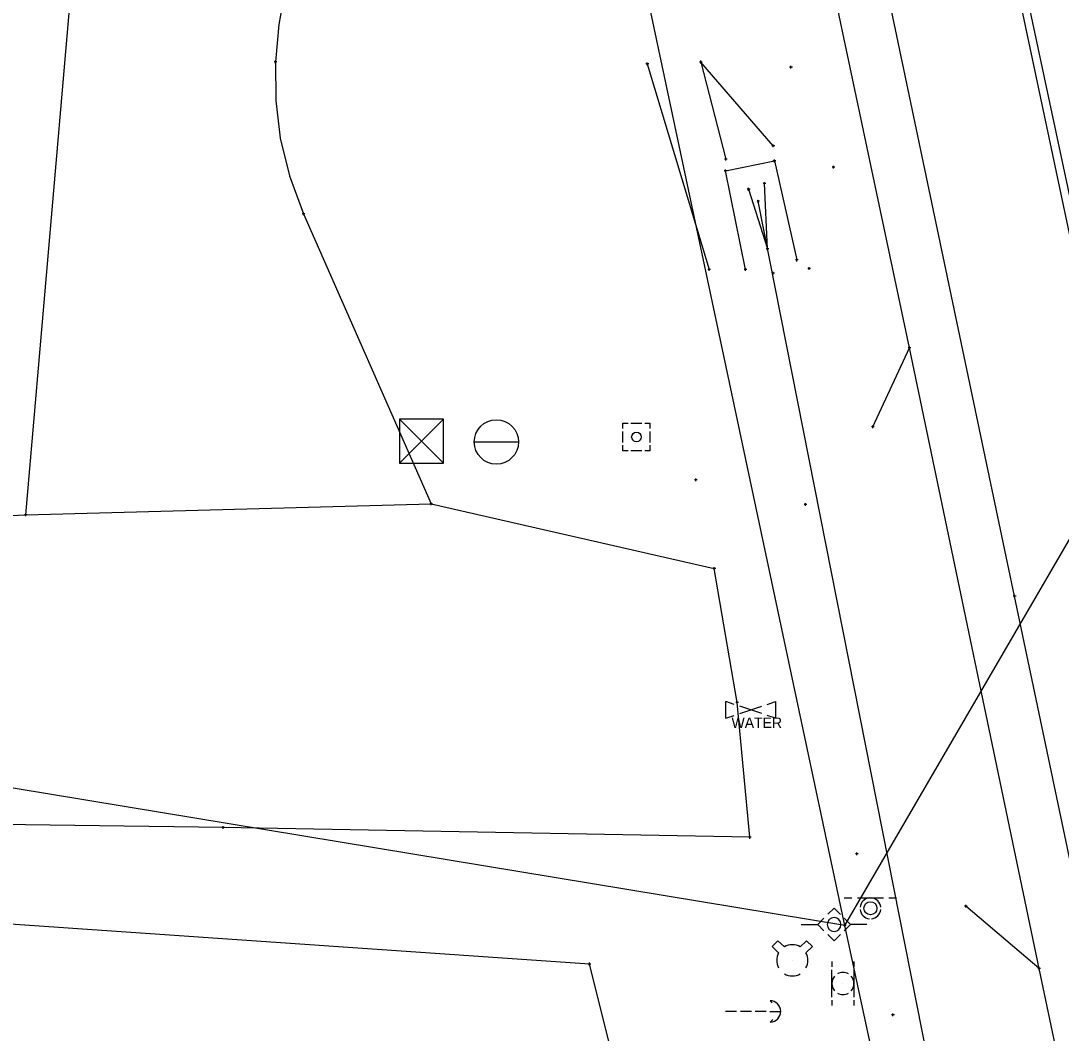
# Model space of a CAD drawing. Extents: x 1954856 to 2011933, y 399149 to 426294.
# Drawn here: x 2005370.7 to 2005465.1, y 405686.9 to 405778.8 of the extents above; entities that cross this region are included whole.
import ezdxf

# ---------------------------------------------------------------- set-up
doc = ezdxf.new("R2010")
doc.units = 0
for name, color, linetype in [('BankMent_ep', 7, 'Continuous'), ('BaselineSurvey', 7, 'Continuous'), ('DelineatorPost_ep', 7, 'Continuous'), ('Driveway_ep', 7, 'Continuous'), ('ElecAer_ep', 7, 'Continuous'), ('EndTreatMES_ep', 7, 'Continuous'), ('FireHydrant_ep', 7, 'Continuous'), ('FlowLineInvert_ep', 7, 'Continuous'), ('GuyWireAnchor_ep', 7, 'Continuous'), ('MonumentOM_ep', 7, 'Continuous'), ('MonumentPST_ep', 7, 'Continuous'), ('PavtAsphalt_ep', 7, 'Continuous'), ('PavtAsphaltCrown_ep', 7, 'Continuous'), ('PipeCulvert_ep', 7, 'Continuous'), ('PointLocator_ep', 7, 'Continuous'), ('PoleShared_ep', 7, 'Continuous'), ('ShldrPaved_ep', 7, 'Continuous'), ('SignSingle_ep', 7, 'Continuous'), ('TelePed_ep', 7, 'Continuous'), ('Trail_ep', 7, 'Continuous'), ('TreeLineScatter_ep', 7, 'Continuous'), ('ValveWater_ep', 7, 'Continuous')]:
    doc.layers.add(name, color=color, linetype=linetype)

msp = doc.modelspace()

# ---------------------------------------------------------------- linework, layer by layer
at = {"layer": 'BankMent_ep'}
msp.add_line((2005427.558, 405774.906), (2005433.178, 405756.239), dxfattribs=at)
msp.add_lwpolyline([(2005438.996, 405767.47), (2005432.422, 405775.077), (2005434.694, 405766.254)], dxfattribs=at)
at = {"layer": 'BaselineSurvey'}
msp.add_line((2006223.925, 402174.382), (2005094.479, 407516.047), dxfattribs=at)
msp.add_line((2006223.925, 402174.382), (2005094.479, 407516.047), dxfattribs=at)
at = {"layer": 'DelineatorPost_ep'}
for p, q in [((2005444.314, 405693.447), (2005444.314, 405692.947)), ((2005446.314, 405693.447), (2005446.314, 405692.947)), ((2005444.314, 405690.197), (2005444.314, 405692.697)), ((2005446.314, 405692.697), (2005446.314, 405690.197)), ((2005445.314, 405691.447), (2005445.314, 405691.447)), ((2005444.314, 405689.947), (2005444.314, 405689.447)), ((2005446.314, 405689.947), (2005446.314, 405689.447))]:
    msp.add_line(p, q, dxfattribs=at)
for start, end in [(138.59038, 221.40962), (60, 120), (318.59038, 41.40962), (240, 300)]:
    msp.add_arc((2005445.314, 405691.447), 1, start, end, dxfattribs=at)
at = {"layer": 'Driveway_ep'}
for p, q in [((2005371.12, 405733.975), (2005375.351, 405782.839)), ((2005396.341, 405761.312), (2005407.925, 405734.989)), ((2005448.023, 405741.963), (2005451.367, 405749.131)), ((2005435.705, 405716.948), (2005433.64, 405729.119)), ((2005436.858, 405704.714), (2005435.705, 405716.948)), ((2005463.131, 405692.797), (2005456.475, 405698.46))]:
    msp.add_line(p, q, dxfattribs=at)
msp.add_lwpolyline([(2005417.945, 405803.487), (2005414.759, 405802.733), (2005411.798, 405801.807), (2005409.062, 405800.694), (2005406.551, 405799.379), (2005404.264, 405797.848), (2005402.2, 405796.084), (2005400.36, 405794.072), (2005398.482, 405791.387), (2005396.914, 405788.413), (2005395.658, 405785.222), (2005394.716, 405781.888), (2005394.092, 405778.485), (2005393.787, 405775.084), (2005393.817, 405771.592), (2005394.232, 405768.153), (2005395.062, 405764.737), (2005396.341, 405761.312)], dxfattribs=at)
at = {"layer": 'ElecAer_ep'}
for points in [[(2005445.498, 405696.718), (2005374.403, 406031.294), (2005427.328, 406130.782), (2005454.704, 406142.236)], [(2005445.498, 405696.718), (2005506.92, 405802.26), (2005520.719, 405804.021)], [(2005486.91, 405504.756), (2005445.498, 405696.718), (2005301.203, 405720.515)]]:
    msp.add_lwpolyline(points, dxfattribs=at)
at = {"layer": 'EndTreatMES_ep'}
for p, q in [((2005434.655, 405765.204), (2005439.091, 405766.098)), ((2005439.091, 405766.098), (2005441.134, 405757.112)), ((2005436.466, 405756.253), (2005434.655, 405765.204))]:
    msp.add_line(p, q, dxfattribs=at)
msp.add_lwpolyline([(2005436.758, 405763.527), (2005438.46, 405758.117), (2005438.204, 405764.048)], dxfattribs=at)
at = {"layer": 'FireHydrant_ep'}
for p, q in [((2005438.893, 405694.794), (2005439.418, 405695.331)), ((2005438.893, 405694.794), (2005439.478, 405694.228)), ((2005439.418, 405695.331), (2005440.001, 405694.768)), ((2005442.021, 405695.328), (2005441.441, 405694.768)), ((2005442.546, 405694.791), (2005441.964, 405694.228)), ((2005442.546, 405694.791), (2005442.021, 405695.328)), ((2005440.721, 405693.547), (2005440.721, 405693.547))]:
    msp.add_line(p, q, dxfattribs=at)
for start, end in [(59.47352, 120.52648), (151.26736, 208.73264), (331.26736, 28.73264), (239.47352, 300.52648)]:
    msp.add_arc((2005440.721, 405693.547), 1.417, start, end, dxfattribs=at)
at = {"layer": 'FlowLineInvert_ep'}
for p, q in [((2005437.713, 405762.355), (2005437.537, 405762.531)), ((2005437.713, 405762.531), (2005437.537, 405762.355)), ((2005437.625, 405762.443), (2005437.625, 405762.443))]:
    msp.add_line(p, q, dxfattribs=at)
at = {"layer": 'GuyWireAnchor_ep'}
for p, q in [((2005438.697, 405689.887), (2005438.89, 405689.694)), ((2005434.67, 405688.924), (2005435.67, 405688.924)), ((2005436.003, 405688.924), (2005437.003, 405688.924)), ((2005437.337, 405688.924), (2005438.337, 405688.924)), ((2005438.67, 405688.914), (2005439.67, 405688.914)), ((2005438.712, 405687.941), (2005438.95, 405688.174)), ((2005439.67, 405688.914), (2005439.67, 405688.914))]:
    msp.add_line(p, q, dxfattribs=at)
msp.add_arc((2005438.697, 405688.914), 0.973, 271.13997, 90.0059, dxfattribs=at)
at = {"layer": 'MonumentOM_ep'}
for p, q in [((2005411.841, 405740.594), (2005415.859, 405740.594)), ((2005413.85, 405740.594), (2005413.85, 405740.594))]:
    msp.add_line(p, q, dxfattribs=at)
msp.add_circle((2005413.85, 405740.594), 2.009, dxfattribs=at)
at = {"layer": 'MonumentPST_ep'}
for p, q in [((2005405.047, 405742.672), (2005409.051, 405738.668)), ((2005405.047, 405738.668), (2005409.051, 405742.672)), ((2005407.049, 405740.67), (2005407.049, 405740.67))]:
    msp.add_line(p, q, dxfattribs=at)
msp.add_lwpolyline([(2005405.047, 405738.668), (2005409.051, 405738.668), (2005409.051, 405742.672), (2005405.047, 405742.672), (2005405.047, 405738.668)], dxfattribs=at)
at = {"layer": 'PavtAsphalt_ep'}
msp.add_lwpolyline([(2005647.527, 404845.36), (2005626.419, 404943.283), (2005605.825, 405041.291), (2005585.161, 405139.301), (2005564.569, 405237.066), (2005543.611, 405334.993), (2005527.25, 405416.168), (2005502.474, 405530.372), (2005481.578, 405628.348), (2005460.909, 405726.598), (2005440.426, 405824.017), (2005419.925, 405921.902), (2005399.287, 406019.762)], dxfattribs=at)
at = {"layer": 'PavtAsphaltCrown_ep'}
msp.add_lwpolyline([(2005659.531, 404847.945), (2005638.673, 404945.697), (2005617.909, 405043.694), (2005597.24, 405141.46), (2005576.514, 405239.298), (2005555.953, 405336.916), (2005535.174, 405434.816), (2005514.411, 405532.803), (2005493.563, 405630.595), (2005473.232, 405728.595), (2005452.357, 405826.425), (2005431.937, 405924.199), (2005411.143, 406022.056)], dxfattribs=at)
at = {"layer": 'PipeCulvert_ep'}
msp.add_lwpolyline([(2005456.117, 405668.938), (2005437.625, 405762.443)], dxfattribs=at)
at = {"layer": 'PointLocator_ep'}
for p, q in [((2005393.912, 405775.084), (2005393.662, 405775.084)), ((2005393.787, 405774.959), (2005393.787, 405775.209)), ((2005393.787, 405775.084), (2005393.787, 405775.084)), ((2005427.683, 405774.906), (2005427.433, 405774.906)), ((2005427.558, 405774.781), (2005427.558, 405775.031)), ((2005427.558, 405774.906), (2005427.558, 405774.906)), ((2005432.547, 405775.077), (2005432.297, 405775.077)), ((2005432.422, 405774.952), (2005432.422, 405775.202)), ((2005432.422, 405775.077), (2005432.422, 405775.077)), ((2005440.726, 405774.618), (2005440.476, 405774.618)), ((2005440.601, 405774.493), (2005440.601, 405774.743)), ((2005440.601, 405774.618), (2005440.601, 405774.618)), ((2005439.121, 405767.47), (2005438.871, 405767.47)), ((2005438.996, 405767.345), (2005438.996, 405767.595)), ((2005438.996, 405767.47), (2005438.996, 405767.47)), ((2005434.819, 405766.254), (2005434.569, 405766.254)), ((2005434.694, 405766.129), (2005434.694, 405766.379)), ((2005434.694, 405766.254), (2005434.694, 405766.254)), ((2005439.216, 405766.098), (2005438.966, 405766.098)), ((2005439.091, 405765.973), (2005439.091, 405766.223)), ((2005439.091, 405766.098), (2005439.091, 405766.098)), ((2005444.585, 405765.545), (2005444.335, 405765.545)), ((2005444.46, 405765.42), (2005444.46, 405765.67)), ((2005444.46, 405765.545), (2005444.46, 405765.545)), ((2005434.78, 405765.204), (2005434.53, 405765.204)), ((2005434.655, 405765.079), (2005434.655, 405765.329)), ((2005434.655, 405765.204), (2005434.655, 405765.204)), ((2005436.758, 405763.402), (2005436.758, 405763.652)), ((2005438.329, 405764.048), (2005438.079, 405764.048)), ((2005438.204, 405763.923), (2005438.204, 405764.173)), ((2005438.204, 405764.048), (2005438.204, 405764.048)), ((2005436.883, 405763.527), (2005436.633, 405763.527)), ((2005436.758, 405763.527), (2005436.758, 405763.527)), ((2005396.466, 405761.312), (2005396.216, 405761.312)), ((2005396.341, 405761.187), (2005396.341, 405761.437)), ((2005396.341, 405761.312), (2005396.341, 405761.312)), ((2005438.585, 405758.117), (2005438.335, 405758.117)), ((2005438.46, 405757.992), (2005438.46, 405758.242)), ((2005438.46, 405758.117), (2005438.46, 405758.117)), ((2005441.259, 405757.112), (2005441.009, 405757.112)), ((2005441.134, 405756.987), (2005441.134, 405757.237)), ((2005441.134, 405757.112), (2005441.134, 405757.112)), ((2005433.303, 405756.239), (2005433.053, 405756.239)), ((2005433.178, 405756.114), (2005433.178, 405756.364)), ((2005433.178, 405756.239), (2005433.178, 405756.239)), ((2005436.591, 405756.253), (2005436.341, 405756.253)), ((2005436.466, 405756.128), (2005436.466, 405756.378)), ((2005436.466, 405756.253), (2005436.466, 405756.253)), ((2005438.974, 405755.799), (2005438.974, 405756.049)), ((2005442.368, 405756.337), (2005442.118, 405756.337)), ((2005442.243, 405756.212), (2005442.243, 405756.462)), ((2005442.243, 405756.337), (2005442.243, 405756.337)), ((2005439.099, 405755.924), (2005438.849, 405755.924)), ((2005438.974, 405755.924), (2005438.974, 405755.924)), ((2005451.492, 405749.131), (2005451.242, 405749.131)), ((2005451.367, 405749.006), (2005451.367, 405749.256)), ((2005451.367, 405749.131), (2005451.367, 405749.131)), ((2005448.148, 405741.963), (2005447.898, 405741.963)), ((2005448.023, 405741.838), (2005448.023, 405742.088)), ((2005448.023, 405741.963), (2005448.023, 405741.963)), ((2005432.089, 405737.167), (2005431.839, 405737.167)), ((2005431.964, 405737.042), (2005431.964, 405737.292)), ((2005431.964, 405737.167), (2005431.964, 405737.167)), ((2005408.05, 405734.989), (2005407.8, 405734.989)), ((2005407.925, 405734.864), (2005407.925, 405735.114)), ((2005407.925, 405734.989), (2005407.925, 405734.989)), ((2005442.038, 405734.931), (2005441.788, 405734.931)), ((2005441.913, 405734.806), (2005441.913, 405735.056)), ((2005441.913, 405734.931), (2005441.913, 405734.931)), ((2005371.245, 405733.975), (2005370.995, 405733.975)), ((2005371.12, 405733.85), (2005371.12, 405734.1)), ((2005371.12, 405733.975), (2005371.12, 405733.975)), ((2005433.765, 405729.119), (2005433.515, 405729.119)), ((2005433.64, 405728.994), (2005433.64, 405729.244)), ((2005433.64, 405729.119), (2005433.64, 405729.119)), ((2005460.909, 405726.473), (2005460.909, 405726.723)), ((2005461.034, 405726.598), (2005460.784, 405726.598)), ((2005460.909, 405726.598), (2005460.909, 405726.598)), ((2005435.83, 405716.948), (2005435.58, 405716.948)), ((2005435.705, 405716.823), (2005435.705, 405717.073)), ((2005435.705, 405716.948), (2005435.705, 405716.948)), ((2005389.167, 405705.615), (2005388.917, 405705.615)), ((2005389.042, 405705.49), (2005389.042, 405705.74)), ((2005389.042, 405705.615), (2005389.042, 405705.615)), ((2005436.983, 405704.714), (2005436.733, 405704.714)), ((2005436.858, 405704.589), (2005436.858, 405704.839)), ((2005436.858, 405704.714), (2005436.858, 405704.714)), ((2005446.711, 405703.21), (2005446.461, 405703.21)), ((2005446.586, 405703.085), (2005446.586, 405703.335)), ((2005446.586, 405703.21), (2005446.586, 405703.21)), ((2005456.6, 405698.46), (2005456.35, 405698.46)), ((2005456.475, 405698.335), (2005456.475, 405698.585)), ((2005456.475, 405698.46), (2005456.475, 405698.46)), ((2005445.623, 405696.718), (2005445.373, 405696.718)), ((2005445.498, 405696.593), (2005445.498, 405696.843)), ((2005445.498, 405696.718), (2005445.498, 405696.718)), ((2005422.43, 405693.214), (2005422.18, 405693.214)), ((2005422.305, 405693.089), (2005422.305, 405693.339)), ((2005422.305, 405693.214), (2005422.305, 405693.214)), ((2005463.256, 405692.797), (2005463.006, 405692.797)), ((2005463.131, 405692.672), (2005463.131, 405692.922)), ((2005463.131, 405692.797), (2005463.131, 405692.797)), ((2005449.986, 405688.614), (2005449.736, 405688.614)), ((2005449.861, 405688.489), (2005449.861, 405688.739)), ((2005449.861, 405688.614), (2005449.861, 405688.614))]:
    msp.add_line(p, q, dxfattribs=at)
at = {"layer": 'PoleShared_ep'}
for p, q in [((2005441.528, 405696.802), (2005443.028, 405696.802)), ((2005443.028, 405696.802), (2005443.595, 405697.369)), ((2005443.59, 405696.241), (2005443.028, 405696.802)), ((2005444.516, 405696.802), (2005444.516, 405696.802)), ((2005447.504, 405696.802), (2005446.004, 405696.802))]:
    msp.add_line(p, q, dxfattribs=at)
for points in [[(2005443.951, 405697.725), (2005444.516, 405698.29), (2005445.083, 405697.723)], [(2005445.438, 405697.368), (2005446.004, 405696.802), (2005445.437, 405696.235)], [(2005445.083, 405695.881), (2005444.516, 405695.314), (2005443.949, 405695.881)]]:
    msp.add_lwpolyline(points, dxfattribs=at)
for start, end in [(90, 270), (270, 90)]:
    msp.add_arc((2005444.516, 405696.802), 0.625, start, end, dxfattribs=at)
at = {"layer": 'ShldrPaved_ep'}
msp.add_lwpolyline([(2005642.79, 404844.426), (2005626.089, 404922.973), (2005619.586, 404953.5), (2005603.976, 405028.203), (2005595.201, 405068.867), (2005580.618, 405138.253), (2005559.729, 405235.858), (2005538.961, 405333.935), (2005522.845, 405410.169), (2005520.122, 405422.327), (2005518.168, 405431.543), (2005497.797, 405529.428), (2005476.915, 405627.442), (2005463.131, 405692.797), (2005451.367, 405749.131), (2005441.124, 405797.497), (2005431.885, 405841.855), (2005414.859, 405921.033), (2005394.473, 406019.032)], dxfattribs=at)
at = {"layer": 'SignSingle_ep'}
for p, q in [((2005445.441, 405699.223), (2005446.141, 405699.223)), ((2005446.641, 405699.223), (2005448.991, 405699.223)), ((2005449.491, 405699.223), (2005450.191, 405699.223)), ((2005447.816, 405698.273), (2005447.816, 405698.273))]:
    msp.add_line(p, q, dxfattribs=at)
msp.add_circle((2005447.816, 405698.273), 0.594, dxfattribs=at)
for start, end in [(96.04233, 173.95767), (6.04233, 83.95767), (186.04233, 263.95767), (276.04233, 353.95767)]:
    msp.add_arc((2005447.816, 405698.273), 0.95, start, end, dxfattribs=at)
at = {"layer": 'TelePed_ep'}
for p, q in [((2005425.324, 405742.304), (2005425.824, 405742.304)), ((2005425.324, 405741.804), (2005425.324, 405742.304)), ((2005426.074, 405742.304), (2005427.074, 405742.304)), ((2005427.324, 405742.304), (2005427.824, 405742.304)), ((2005427.824, 405741.804), (2005427.824, 405742.304)), ((2005425.324, 405740.554), (2005425.324, 405741.554)), ((2005426.574, 405741.054), (2005426.574, 405741.054)), ((2005427.824, 405740.554), (2005427.824, 405741.554)), ((2005425.324, 405739.804), (2005425.324, 405740.304)), ((2005427.824, 405739.804), (2005427.824, 405740.304)), ((2005425.824, 405739.804), (2005425.324, 405739.804)), ((2005427.074, 405739.804), (2005426.074, 405739.804)), ((2005427.824, 405739.804), (2005427.324, 405739.804))]:
    msp.add_line(p, q, dxfattribs=at)
msp.add_circle((2005426.574, 405741.054), 0.438, dxfattribs=at)
at = {"layer": 'Trail_ep'}
for points in [[(2005300.132, 405730.93), (2005371.12, 405733.975), (2005407.925, 405734.989), (2005433.64, 405729.119)], [(2005436.858, 405704.714), (2005389.042, 405705.615), (2005303.684, 405706.751)]]:
    msp.add_lwpolyline(points, dxfattribs=at)
at = {"layer": 'TreeLineScatter_ep'}
msp.add_lwpolyline([(2005459.854, 405543.214), (2005422.305, 405693.214), (2005304.819, 405701.308)], dxfattribs=at)
at = {"layer": 'ValveWater_ep'}
for p, q in [((2005435.443, 405716.777), (2005434.693, 405717.027)), ((2005434.693, 405715.527), (2005434.693, 405717.027)), ((2005437.943, 405715.944), (2005435.943, 405716.61)), ((2005435.943, 405715.944), (2005437.943, 405716.61)), ((2005438.443, 405716.777), (2005439.193, 405717.027)), ((2005439.193, 405717.027), (2005439.193, 405715.527)), ((2005434.693, 405715.527), (2005435.443, 405715.777)), ((2005436.943, 405716.277), (2005436.943, 405716.277)), ((2005439.193, 405715.527), (2005438.443, 405715.777))]:
    msp.add_line(p, q, dxfattribs=at)

# ---------------------------------------------------------------- texts
msp.add_text('WATER', height=0.95, dxfattribs=at).set_placement((2005435.205, 405714.638))

doc.saveas('drawing.dxf')
